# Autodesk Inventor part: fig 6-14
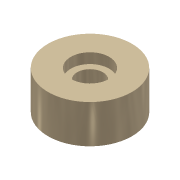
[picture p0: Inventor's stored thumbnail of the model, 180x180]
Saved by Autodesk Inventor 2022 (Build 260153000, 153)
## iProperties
Created: 2001-11
Part Number: fig 6-14
Document SubType Name: Modeling
Designer: Renu Muthoo
Density: 1 g/cm^3
Material: Generic
Appearance: Metal-Titanium (Polished)
Control State: 0
Master: False
Checked Out: False
Shininess: 65.0
Angle Display Precision: 2
Document Length Units: 11269
Document Angle Units: 11279
Document Time Units: 11290
Document Mass Units: 11283
Document Length Units Precision: 3
Document Angle Units Precision: 2
Density: 0.0
Volumn: 0.0
Area: 0.0
PropertySet Name: Model Information
Author: Renu Muthoo
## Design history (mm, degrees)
sketch "Sketch1"
  geometry: C1 r 16.401 at (0, 0)
  constraints: 1 centre point
extrude "Extrusion1" new body sketch "Sketch1" distance "d0" = 15; taper "d1" = 0 deg
hole "Hole3" diameter "d18" = 10.106; stored, may be unused: countersink angle "d22" = 90 deg, drill point angle "d24" = 118 deg; dims "d16" = 10, "d17" = 10, "d19" = 6, "d20" = 15, "d21" = 4, "d23" = 10
body "Solid1"
